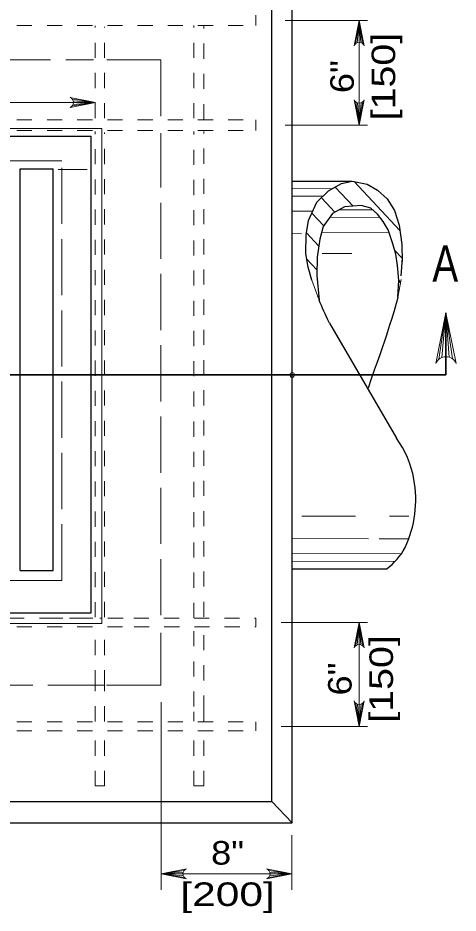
# Model space of a CAD drawing. Extents: x 1083.1 to 1117.1, y 697.4 to 719.4.
# Drawn here: x 1105.05 to 1107.97, y 709.39 to 715.32 of the extents above; entities that cross this region are included whole.
import ezdxf
from ezdxf.enums import TextEntityAlignment as Align

# ---------------------------------------------------------------- set-up
doc = ezdxf.new("R2010")
doc.units = 0
doc.header["$LTSCALE"] = 0.062
doc.header["$PDMODE"] = 32
doc.header["$PDSIZE"] = 0.031
doc.linetypes.add('DOTTED', pattern=[1.5, 0.3, -1.2])
doc.linetypes.add('LONG_DASHED', pattern=[7.5, 6, -1.5])
doc.layers.add('1', color=7, linetype='Continuous', lineweight=13)

msp = doc.modelspace()

# ---------------------------------------------------------------- linework, layer by layer
at = {"layer": '1', "lineweight": 25}
for p, q in [((1106.86575, 709.98508), (1106.86575, 715.96917)), ((1106.73117, 710.1275), (1106.73117, 715.82667)), ((1102.55767, 714.53308), (1105.5345, 714.53308)), ((1105.5345, 711.37625), (1105.5345, 714.53308)), ((1105.06258, 714.31583), (1105.2815, 714.31583)), ((1105.06258, 712.7495), (1105.06258, 714.31583)), ((1105.2815, 711.65625), (1105.2815, 714.31583)), ((1106.86758, 714.23483), (1107.26308, 714.23425)), ((1107.26308, 714.23425), (1107.36308, 714.21483)), ((1107.594, 713.72508), (1107.5865, 713.60808)), ((1107.11225, 713.29467), (1107.55675, 712.53175)), ((1105.06258, 712.43633), (1105.06258, 712.7495)), ((1105.06258, 711.73258), (1105.06258, 712.44542)), ((1105.06258, 711.65625), (1105.06258, 711.73258)), ((1105.06258, 711.65625), (1105.2815, 711.65625)), ((1106.86383, 711.66858), (1107.4925, 711.66767)), ((1105.21817, 711.37625), (1105.5345, 711.37625)), ((1101.34808, 710.1275), (1106.73117, 710.1275)), ((1106.73117, 710.1275), (1106.86575, 709.98508)), ((1101.2135, 709.98508), (1106.86575, 709.98508))]:
    msp.add_line(p, q, dxfattribs=at)
at = {"layer": '1', "linetype": 'DOTTED'}
for p, q in [((1106.624, 715.26525), (1106.624, 715.33383)), ((1101.44158, 715.26525), (1106.624, 715.26525)), ((1105.56117, 714.65133), (1105.56117, 715.26242)), ((1105.62242, 714.65133), (1105.62242, 715.25667)), ((1106.21342, 714.65133), (1106.21342, 715.26525)), ((1106.28092, 714.6455), (1106.28092, 715.26525)), ((1106.28092, 714.688), (1106.28092, 714.689)), ((1101.44158, 714.64142), (1106.624, 714.64142)), ((1106.624, 714.56992), (1106.624, 714.64142)), ((1101.44158, 714.56992), (1106.624, 714.56992)), ((1105.56117, 711.34633), (1105.56117, 714.56267)), ((1106.21342, 711.34267), (1106.21342, 714.56267)), ((1106.28092, 711.35), (1106.28092, 714.56458)), ((1105.62242, 711.34817), (1105.62242, 714.55675)), ((1105.24525, 711.341), (1105.81633, 711.341)), ((1105.81633, 711.341), (1106.624, 711.341)), ((1106.624, 711.28275), (1106.624, 711.341)), ((1105.56117, 710.89625), (1105.56117, 711.28033)), ((1105.62242, 710.89625), (1105.62242, 711.27658)), ((1106.21342, 710.75483), (1106.21342, 711.27658)), ((1105.56117, 710.65733), (1105.56117, 710.9355)), ((1105.62242, 710.65733), (1105.62242, 710.92667)), ((1106.21342, 710.65875), (1106.21342, 710.72)), ((1101.44158, 710.6545), (1106.624, 710.6545)), ((1106.624, 710.59433), (1106.624, 710.6545)), ((1101.44158, 710.59433), (1106.624, 710.59433)), ((1105.56117, 710.22967), (1105.56117, 710.59375)), ((1105.62242, 710.22967), (1105.62242, 710.59483)), ((1106.21342, 710.22967), (1106.21342, 710.589)), ((1106.28092, 710.22967), (1106.28092, 710.589)), ((1105.56117, 710.22967), (1105.62242, 710.22967)), ((1106.21342, 710.22967), (1106.28092, 710.22967))]:
    msp.add_line(p, q, dxfattribs=at)
at = {"layer": '1'}
for p, q in [((1106.81883, 715.2995), (1107.36525, 715.2995)), ((1107.286, 715.14542), (1107.30958, 715.2995)), ((1107.29592, 715.15125), (1107.30958, 715.2995)), ((1107.30958, 715.154), (1107.30958, 715.2995)), ((1107.32033, 715.15242), (1107.30958, 715.2995)), ((1107.33092, 715.14725), (1107.30958, 715.2995)), ((1107.30958, 715.2995), (1107.30958, 714.60567)), ((1105.562, 714.75608), (1102.51208, 714.75608)), ((1105.40792, 714.73258), (1105.562, 714.75608)), ((1105.40967, 714.77742), (1105.562, 714.75608)), ((1105.41375, 714.74242), (1105.562, 714.75608)), ((1105.41483, 714.76683), (1105.562, 714.75608)), ((1105.41642, 714.75608), (1105.562, 714.75608)), ((1107.28825, 714.758), (1107.30958, 714.60567)), ((1107.29883, 714.75283), (1107.30958, 714.60567)), ((1107.33317, 714.75975), (1107.30958, 714.60567)), ((1107.32325, 714.75392), (1107.30958, 714.60567)), ((1107.30958, 714.75125), (1107.30958, 714.60567)), ((1106.81883, 714.60567), (1107.36525, 714.60567)), ((1105.31592, 714.31092), (1105.50758, 714.31092)), ((1107.27608, 714.23158), (1107.58, 713.909)), ((1107.36308, 714.21483), (1107.43208, 714.17425)), ((1106.86742, 714.18517), (1107.13208, 714.18467)), ((1107.15117, 714.19525), (1107.2695, 714.06967)), ((1106.86742, 714.1355), (1107.071, 714.13517)), ((1107.0595, 714.12367), (1107.149, 714.02867)), ((1106.86733, 714.036), (1107.00267, 714.03583)), ((1107.17783, 714.04525), (1107.39917, 714.04492)), ((1106.99625, 714.02192), (1107.07533, 713.93808)), ((1107.11608, 713.99558), (1107.44758, 713.995)), ((1106.867, 713.887), (1106.92725, 713.88675)), ((1106.95692, 713.75608), (1106.95758, 713.87933)), ((1106.95967, 713.89175), (1107.04258, 713.80383)), ((1107.062, 713.89625), (1107.50833, 713.89558)), ((1107.06458, 713.75542), (1107.26142, 713.75508)), ((1107.54475, 713.77725), (1107.594, 713.72508)), ((1106.96333, 713.71917), (1107.02992, 713.64825)), ((1107.04442, 713.44667), (1106.99625, 713.57825)), ((1107.04442, 713.44667), (1106.99625, 713.57825)), ((1107.58725, 713.58358), (1107.56567, 713.46592)), ((1107.58725, 713.58358), (1107.56567, 713.46592)), ((1107.57167, 713.57992), (1107.58425, 713.56675)), ((1107.57183, 713.57492), (1107.58342, 713.56242)), ((1107.56808, 713.50842), (1107.57267, 713.50367)), ((1107.03433, 713.47475), (1107.04267, 713.46567)), ((1107.04192, 713.45358), (1107.04417, 713.45142)), ((1107.83767, 713.05483), (1107.88475, 713.363)), ((1107.85742, 713.0665), (1107.88475, 713.363)), ((1107.88475, 713.07183), (1107.88475, 713.363)), ((1107.90633, 713.06867), (1107.88475, 713.363)), ((1107.92742, 713.05842), (1107.88475, 713.363)), ((1106.92867, 712.01633), (1107.28633, 712.01583)), ((1107.51158, 712.0155), (1107.63842, 712.01533)), ((1106.86425, 711.86742), (1107.37125, 711.86658)), ((1107.44125, 711.86658), (1107.63825, 711.86625)), ((1106.864, 711.768), (1107.58875, 711.76683)), ((1106.864, 711.71833), (1107.5485, 711.71708)), ((1106.7925, 711.31183), (1107.36525, 711.31183)), ((1107.286, 711.15775), (1107.30958, 711.31183)), ((1107.29592, 711.16358), (1107.30958, 711.31183)), ((1107.30958, 711.16625), (1107.30958, 711.31183)), ((1107.32033, 711.16475), (1107.30958, 711.31183)), ((1107.33092, 711.15958), (1107.30958, 711.31183)), ((1107.30958, 711.31183), (1107.30958, 710.62442)), ((1105.99675, 710.78442), (1105.99675, 709.54108)), ((1107.28825, 710.77667), (1107.30958, 710.62442)), ((1107.29883, 710.7715), (1107.30958, 710.62442)), ((1107.33317, 710.7785), (1107.30958, 710.62442)), ((1107.32325, 710.77267), (1107.30958, 710.62442)), ((1107.30958, 710.77), (1107.30958, 710.62442)), ((1106.7925, 710.62442), (1107.36525, 710.62442)), ((1106.86433, 709.90283), (1106.86433, 709.54108)), ((1106.149, 709.66933), (1105.99675, 709.648)), ((1106.14392, 709.65875), (1105.99675, 709.648)), ((1105.99675, 709.648), (1106.86433, 709.648)), ((1106.14233, 709.648), (1105.99675, 709.648)), ((1106.145, 709.63433), (1105.99675, 709.648)), ((1106.15083, 709.6245), (1105.99675, 709.648)), ((1106.71025, 709.6245), (1106.86433, 709.648)), ((1106.712, 709.66933), (1106.86433, 709.648)), ((1106.71608, 709.63433), (1106.86433, 709.648)), ((1106.71717, 709.65875), (1106.86433, 709.648)), ((1106.71875, 709.648), (1106.86433, 709.648))]:
    msp.add_line(p, q, dxfattribs=at)
at = {"layer": '1', "linetype": 'LONG_DASHED'}
for p, q in [((1102.53292, 715.03767), (1105.54933, 715.03767)), ((1105.63858, 715.03767), (1105.99567, 715.03767)), ((1105.99567, 714.66508), (1105.99567, 715.03767)), ((1105.99567, 711.36), (1105.99567, 714.55333)), ((1105.33825, 714.37), (1104.5145, 714.37)), ((1105.33825, 711.591), (1105.33825, 714.37)), ((1102.8875, 710.89625), (1105.6355, 710.89625))]:
    msp.add_line(p, q, dxfattribs=at)
at = {"layer": '1', "lineweight": 35}
for p in [(1107.88475, 713.363), (1102.81875, 712.95175)]:
    msp.add_line(p, (1107.88475, 712.95175), dxfattribs=at)
at = {"layer": '1'}
for points in [[(1107.27592, 715.13133), (1107.30958, 715.2995), (1107.34325, 715.13133)], [(1105.39375, 714.7225), (1105.562, 714.75608), (1105.39375, 714.78975)], [(1107.34325, 714.77392), (1107.30958, 714.60567), (1107.27592, 714.77392)], [(1107.03008, 714.09492), (1107.10725, 714.17092), (1107.193, 714.21867), (1107.26308, 714.23425)], [(1107.8175, 713.0265), (1107.88475, 713.363), (1107.95208, 713.0265)], [(1107.27592, 711.14367), (1107.30958, 711.31183), (1107.34325, 711.14367)], [(1107.34325, 710.79258), (1107.30958, 710.62442), (1107.27592, 710.79258)], [(1106.165, 709.61433), (1105.99675, 709.648), (1106.165, 709.68167)], [(1106.69608, 709.61433), (1106.86433, 709.648), (1106.69608, 709.68167)]]:
    msp.add_lwpolyline(points, dxfattribs=at)
msp.add_lwpolyline([(1102.48892, 714.58392), (1102.48892, 711.30575), (1105.60367, 711.30575), (1105.60367, 714.58392)], close=True, dxfattribs=at)
at = {"layer": '1', "lineweight": 25}
for points in [[(1106.99625, 713.57825), (1106.97217, 713.66417), (1106.95692, 713.75608), (1106.95758, 713.87933), (1106.97342, 713.97308), (1107.03008, 714.09492), (1107.10725, 714.17092), (1107.193, 714.21867), (1107.26308, 714.23425), (1107.36308, 714.21483), (1107.43208, 714.17425), (1107.49592, 714.11858), (1107.54417, 714.04067), (1107.57583, 713.94233), (1107.59167, 713.81492), (1107.59483, 713.70058)], [(1107.43208, 714.17425), (1107.49592, 714.11858), (1107.54417, 714.04067), (1107.57583, 713.94233)], [(1106.95758, 713.87933), (1106.97342, 713.97308), (1107.03008, 714.09492)], [(1107.56567, 713.46592), (1107.572, 713.57683), (1107.56292, 713.67542), (1107.55192, 713.75083), (1107.53375, 713.81867), (1107.50292, 713.9115), (1107.46817, 713.96767), (1107.43192, 714.01617), (1107.388, 714.05483), (1107.32217, 714.07433), (1107.21267, 714.06483), (1107.13392, 714.02033), (1107.07183, 713.9335), (1107.04967, 713.85033), (1107.03133, 713.73242), (1107.02925, 713.6105), (1107.04442, 713.44667)], [(1107.56567, 713.46592), (1107.572, 713.57683), (1107.56292, 713.67542), (1107.55192, 713.75083), (1107.53375, 713.81867), (1107.50292, 713.9115), (1107.46817, 713.96767), (1107.43192, 714.01617), (1107.388, 714.05483), (1107.32217, 714.07433), (1107.21267, 714.06483), (1107.13392, 714.02033), (1107.07183, 713.9335), (1107.04967, 713.85033), (1107.03133, 713.73242), (1107.02925, 713.6105), (1107.04442, 713.44667)], [(1106.99625, 713.57825), (1106.97217, 713.66417), (1106.95692, 713.75608)], [(1102.55767, 711.37625), (1103.02333, 711.37625), (1105.21817, 711.37625)]]:
    msp.add_lwpolyline(points, dxfattribs=at)
at = {"layer": '1', "linetype": 'LONG_DASHED'}
for points in [[(1102.719, 711.591), (1104.52517, 711.591), (1105.33825, 711.591)], [(1105.6355, 710.89625), (1105.99567, 710.89625), (1105.99567, 711.24442)]]:
    msp.add_lwpolyline(points, dxfattribs=at)
at = {"layer": '1', "linetype": 'DOTTED'}
for points in [[(1101.44158, 711.341), (1102.9905, 711.341), (1105.60367, 711.341)], [(1101.44158, 711.28275), (1105.81817, 711.28275), (1106.624, 711.28275)], [(1106.28092, 710.65875), (1106.28092, 710.72858), (1106.28092, 711.273)]]:
    msp.add_lwpolyline(points, dxfattribs=at)
at = {"layer": '1'}
for centre, radius, start, end in [((1107.30962, 715.11773), 0.03631, 22.08782, 157.91395), ((1105.38018, 714.75614), 0.03631, 292.08605, 67.91218), ((1107.30955, 714.78748), 0.03631, 202.08782, 337.91395), ((1107.88486, 712.99937), 0.07261, 22.08782, 157.91395), ((1107.30962, 711.13004), 0.03631, 22.08782, 157.91395), ((1107.30955, 710.8062), 0.03631, 202.08782, 337.91395), ((1106.17855, 709.64806), 0.03631, 112.08782, 247.91395), ((1106.68251, 709.64806), 0.03631, 292.08605, 67.91218)]:
    msp.add_arc(centre, radius, start, end, dxfattribs=at)
at = {"layer": '1', "lineweight": 25}
for centre, major_axis, start_param, end_param in [((1107.07287, 712.13725), (0, 0.6467), 4.9058986, 5.3686347), ((1107.00843, 712.1262), (0, 0.71577), 4.251341, 4.9027182), ((1107.25987, 712.0223), (0, -0.43184), 0.6070417, 1.0508543)]:
    msp.add_ellipse(centre, major_axis=major_axis, ratio=0.944544, start_param=start_param, end_param=end_param, dxfattribs=at)
for points in [[(1107.11225, 713.29467), (1107.08558, 713.35075), (1107.06325, 713.40125), (1107.04442, 713.44667)], [(1107.56567, 713.46592), (1107.5405, 713.36342), (1107.48767, 713.19892), (1107.36825, 712.86458)]]:
    msp.add_open_spline(points, degree=3, dxfattribs=at)
at = {"layer": '1'}
msp.add_point((1106.86575, 712.95175), dxfattribs=at)

# ---------------------------------------------------------------- texts
for s, width, p in [('[150]', 1.25, (1107.54833, 714.92692)), ('6"', 1.15, (1107.27425, 714.92692)), ('[150]', 1.25, (1107.53367, 710.93808)), ('6"', 1.15, (1107.25958, 710.93808))]:
    msp.add_text(s, height=0.156, rotation=90, dxfattribs=dict(at, width=width)).set_placement(p, align=Align.CENTER)
at = {"layer": '1', "width": 0.8}
msp.add_text('A', height=0.24, dxfattribs=at).set_placement((1107.79458, 713.56908))
at = {"layer": '1'}
for s, width, p in [('8"', 1.15, (1106.43758, 709.70892)), ('[200]', 1.35, (1106.43758, 709.43483))]:
    msp.add_text(s, height=0.156, dxfattribs=dict(at, width=width)).set_placement(p, align=Align.CENTER)

doc.saveas('drawing.dxf')
